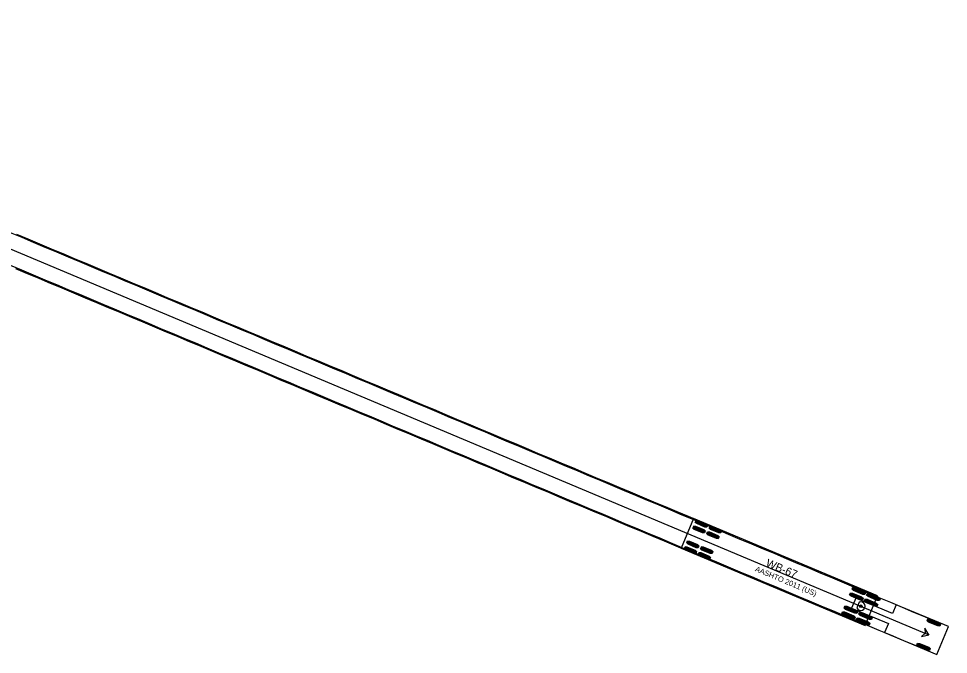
# Model space of a CAD drawing. Extents: x 916040 to 917457, y 328936 to 330267.
# Drawn here: x 917210 to 917456.8, y 329403.5 to 329572.2 of the extents above; entities that cross this region are included whole.
import ezdxf

# ---------------------------------------------------------------- set-up
doc = ezdxf.new("R2010")
doc.units = 0
doc.layers.add('NB_RightontoRoute25_WB67', color=7, linetype='Continuous')
doc.layers.add('NB_ThruontoManchester_WB67', color=7, linetype='Continuous')

msp = doc.modelspace()

# ---------------------------------------------------------------- linework, layer by layer
at = {"layer": 'NB_RightontoRoute25_WB67'}
for p, q in [((917062.28, 329572.24), (917451.54, 329408.71)), ((917389.11, 329439.55), (917385.82, 329431.71)), ((917437.97, 329419.02), (917389.11, 329439.55)), ((917392.67, 329437.31), (917389.63, 329438.59)), ((917392.76, 329437.52), (917389.71, 329438.8)), ((917392.85, 329437.73), (917389.8, 329439.01)), ((917392.03, 329435.79), (917388.99, 329437.06)), ((917392.12, 329436), (917389.08, 329437.28)), ((917392.21, 329436.21), (917389.16, 329437.49)), ((917395.72, 329434.24), (917392.67, 329435.52)), ((917395.81, 329434.45), (917392.76, 329435.73)), ((917395.89, 329434.66), (917392.85, 329435.94)), ((917396.36, 329435.76), (917393.31, 329437.04)), ((917396.44, 329435.97), (917393.4, 329437.25)), ((917396.53, 329436.18), (917393.49, 329437.46)), ((917390.37, 329431.84), (917387.33, 329433.12)), ((917390.46, 329432.05), (917387.42, 329433.33)), ((917390.55, 329432.26), (917387.5, 329433.54)), ((917385.82, 329431.71), (917434.68, 329411.18)), ((917389.73, 329430.32), (917386.69, 329431.59)), ((917389.82, 329430.53), (917386.78, 329431.81)), ((917389.91, 329430.74), (917386.87, 329432.02)), ((917393.6, 329429.19), (917390.55, 329430.47)), ((917394.06, 329430.29), (917391.02, 329431.57)), ((917394.15, 329430.5), (917391.1, 329431.78)), ((917394.24, 329430.71), (917391.19, 329431.99)), ((917393.42, 329428.77), (917390.38, 329430.05)), ((917393.51, 329428.98), (917390.46, 329430.26)), ((917434.6, 329419.42), (917431.22, 329420.84)), ((917434.69, 329419.63), (917431.3, 329421.05)), ((917434.77, 329419.84), (917431.39, 329421.26)), ((917433.96, 329417.9), (917430.58, 329419.32)), ((917434.05, 329418.11), (917430.67, 329419.53)), ((917434.13, 329418.32), (917430.75, 329419.74)), ((917432.18, 329418.4), (917431.07, 329415.76)), ((917441.95, 329414.29), (917432.18, 329418.4)), ((917438.01, 329416.7), (917434.63, 329418.12)), ((917434.68, 329411.18), (917437.97, 329419.02)), ((917438.47, 329417.8), (917435.09, 329419.22)), ((917438.56, 329418.01), (917435.18, 329419.43)), ((917438.65, 329418.22), (917435.27, 329419.64)), ((917437.97, 329419.02), (917437.97, 329419.02)), ((917432.49, 329414.41), (917429.11, 329415.83)), ((917432.58, 329414.62), (917429.2, 329416.04)), ((917432.67, 329414.84), (917429.29, 329416.26)), ((917431.07, 329415.76), (917440.84, 329411.65)), ((917433.13, 329417.32), (917432.5, 329415.83)), ((917437.83, 329416.27), (917434.45, 329417.69)), ((917437.92, 329416.49), (917434.54, 329417.91)), ((917442.95, 329416.66), (917441.95, 329414.29)), ((917456.77, 329410.85), (917442.95, 329416.66)), ((917431.85, 329412.89), (917428.47, 329414.31)), ((917431.94, 329413.1), (917428.56, 329414.52)), ((917432.03, 329413.31), (917428.65, 329414.73)), ((917435.9, 329411.69), (917432.52, 329413.11)), ((917436.36, 329412.79), (917432.98, 329414.21)), ((917436.45, 329413), (917433.07, 329414.42)), ((917436.54, 329413.21), (917433.16, 329414.63)), ((917435.73, 329411.26), (917432.34, 329412.69)), ((917435.81, 329411.48), (917432.43, 329412.9)), ((917440.84, 329411.65), (917439.85, 329409.28)), ((917454.51, 329411.06), (917451.13, 329412.48)), ((917454.6, 329411.27), (917451.22, 329412.69)), ((917454.69, 329411.48), (917451.31, 329412.9)), ((917453.68, 329403.48), (917456.77, 329410.85)), ((917456.77, 329410.85), (917456.77, 329410.85)), ((917439.85, 329409.28), (917453.68, 329403.48)), ((917451.77, 329404.53), (917448.39, 329405.95)), ((917451.86, 329404.74), (917448.48, 329406.16)), ((917451.94, 329404.95), (917448.56, 329406.37))]:
    msp.add_line(p, q, dxfattribs=at)
for points in [[(917207.73, 329515.48), (917210.8, 329514.19), (917213.87, 329512.89), (917216.95, 329511.6), (917220.02, 329510.31), (917223.1, 329509.02), (917226.17, 329507.73), (917229.25, 329506.44), (917232.32, 329505.14), (917235.4, 329503.85), (917238.47, 329502.56), (917241.55, 329501.27), (917244.62, 329499.98), (917247.7, 329498.69), (917250.77, 329497.39), (917253.85, 329496.1), (917256.92, 329494.81), (917260, 329493.52), (917263.07, 329492.23), (917266.14, 329490.94), (917269.22, 329489.64), (917272.29, 329488.35), (917275.37, 329487.06), (917278.44, 329485.77), (917281.52, 329484.48), (917284.59, 329483.19), (917287.67, 329481.89), (917290.74, 329480.6), (917293.82, 329479.31), (917296.89, 329478.02), (917299.97, 329476.73), (917303.04, 329475.44), (917306.12, 329474.14), (917309.19, 329472.85), (917312.27, 329471.56), (917315.34, 329470.27), (917318.41, 329468.98), (917321.49, 329467.69), (917324.56, 329466.39), (917327.64, 329465.1), (917330.71, 329463.81), (917333.79, 329462.52), (917336.86, 329461.23), (917339.94, 329459.93), (917343.01, 329458.64), (917346.09, 329457.35), (917349.16, 329456.06), (917352.24, 329454.77), (917355.31, 329453.48), (917358.39, 329452.18), (917361.46, 329450.89), (917364.54, 329449.6), (917367.61, 329448.31), (917370.68, 329447.02), (917373.76, 329445.73), (917376.83, 329444.43), (917379.91, 329443.14), (917382.98, 329441.85), (917386.06, 329440.56), (917389.13, 329439.27), (917392.21, 329437.98), (917395.28, 329436.68), (917398.36, 329435.39), (917401.43, 329434.1), (917404.51, 329432.81), (917407.58, 329431.52), (917410.66, 329430.23), (917413.73, 329428.93), (917416.81, 329427.64), (917419.88, 329426.35), (917422.95, 329425.06), (917426.03, 329423.77), (917429.1, 329422.48), (917432.18, 329421.18), (917435.25, 329419.89), (917438.33, 329418.6), (917441.4, 329417.31), (917444.48, 329416.02), (917447.55, 329414.73), (917450.63, 329413.43), (917453.09, 329412.4)], [(917209.38, 329515.03), (917212.46, 329513.74), (917215.53, 329512.45), (917218.61, 329511.16), (917221.68, 329509.87), (917224.76, 329508.58), (917227.83, 329507.29), (917230.91, 329506), (917233.98, 329504.71), (917237.06, 329503.42), (917240.13, 329502.12), (917243.21, 329500.83), (917246.28, 329499.54), (917249.36, 329498.25), (917252.43, 329496.96), (917255.51, 329495.67), (917258.58, 329494.38), (917261.66, 329493.09), (917264.73, 329491.79), (917267.81, 329490.5), (917270.88, 329489.21), (917273.96, 329487.92), (917277.03, 329486.63), (917280.11, 329485.34), (917283.18, 329484.05), (917286.26, 329482.75), (917289.33, 329481.46), (917292.41, 329480.17), (917295.48, 329478.88), (917298.55, 329477.59), (917301.63, 329476.3), (917304.7, 329475.01), (917307.78, 329473.71), (917310.85, 329472.42), (917313.93, 329471.13), (917317, 329469.84), (917320.08, 329468.55), (917323.15, 329467.26), (917326.23, 329465.96), (917329.3, 329464.67), (917332.38, 329463.38), (917335.45, 329462.09), (917338.53, 329460.8), (917341.6, 329459.51), (917344.68, 329458.21), (917347.75, 329456.92), (917350.83, 329455.63), (917353.9, 329454.34), (917356.98, 329453.05), (917360.05, 329451.76), (917363.12, 329450.46), (917366.2, 329449.17), (917369.27, 329447.88), (917372.35, 329446.59), (917375.42, 329445.3), (917378.5, 329444.01), (917381.57, 329442.71), (917384.65, 329441.42), (917387.72, 329440.13), (917390.8, 329438.84), (917393.26, 329437.81)], [(917207.7, 329506.81), (917210.78, 329505.52), (917213.85, 329504.23), (917216.93, 329502.94), (917220, 329501.64), (917223.07, 329500.35), (917226.15, 329499.06), (917229.22, 329497.77), (917232.3, 329496.48), (917235.37, 329495.19), (917238.45, 329493.89), (917241.52, 329492.6), (917244.6, 329491.31), (917247.67, 329490.02), (917250.75, 329488.73), (917253.82, 329487.44), (917256.9, 329486.14), (917259.97, 329484.85), (917263.05, 329483.56), (917266.12, 329482.27), (917269.2, 329480.98), (917272.27, 329479.69), (917275.34, 329478.39), (917278.42, 329477.1), (917281.49, 329475.81), (917284.57, 329474.52), (917287.64, 329473.23), (917290.72, 329471.93), (917293.79, 329470.64), (917296.87, 329469.35), (917299.94, 329468.06), (917303.02, 329466.77), (917306.09, 329465.48), (917309.17, 329464.18), (917312.24, 329462.89), (917315.32, 329461.6), (917318.39, 329460.31), (917321.47, 329459.02), (917324.54, 329457.73), (917327.61, 329456.43), (917330.69, 329455.14), (917333.76, 329453.85), (917336.84, 329452.56), (917339.91, 329451.27), (917342.99, 329449.98), (917346.06, 329448.68), (917349.14, 329447.39), (917352.21, 329446.1), (917355.29, 329444.81), (917358.36, 329443.52), (917361.44, 329442.23), (917364.51, 329440.93), (917367.59, 329439.64), (917370.66, 329438.35), (917373.74, 329437.06), (917376.81, 329435.77), (917379.88, 329434.48), (917382.96, 329433.18), (917386.03, 329431.89), (917389.11, 329430.6), (917392.18, 329429.31), (917395.26, 329428.02), (917398.33, 329426.73), (917401.41, 329425.43), (917404.48, 329424.14), (917407.56, 329422.85), (917410.63, 329421.56), (917413.71, 329420.27), (917416.78, 329418.97), (917419.86, 329417.68), (917422.93, 329416.39), (917426.01, 329415.1), (917429.08, 329413.81), (917432.15, 329412.52), (917435.23, 329411.22), (917438.3, 329409.93), (917441.38, 329408.64), (917444.45, 329407.35), (917447.53, 329406.06), (917449.99, 329405.02)], [(917209.17, 329505.9), (917212.24, 329504.61), (917215.32, 329503.32), (917218.39, 329502.03), (917221.47, 329500.74), (917224.54, 329499.45), (917227.62, 329498.16), (917230.69, 329496.87), (917233.77, 329495.58), (917236.84, 329494.29), (917239.92, 329493), (917242.99, 329491.71), (917246.07, 329490.41), (917249.14, 329489.12), (917252.22, 329487.83), (917255.29, 329486.54), (917258.37, 329485.25), (917261.44, 329483.96), (917264.52, 329482.67), (917267.59, 329481.38), (917270.66, 329480.08), (917273.74, 329478.79), (917276.81, 329477.5), (917279.89, 329476.21), (917282.96, 329474.92), (917286.04, 329473.63), (917289.11, 329472.33), (917292.19, 329471.04), (917295.26, 329469.75), (917298.34, 329468.46), (917301.41, 329467.17), (917304.49, 329465.88), (917307.56, 329464.59), (917310.64, 329463.29), (917313.71, 329462), (917316.79, 329460.71), (917319.86, 329459.42), (917322.94, 329458.13), (917326.01, 329456.84), (917329.09, 329455.54), (917332.16, 329454.25), (917335.23, 329452.96), (917338.31, 329451.67), (917341.38, 329450.38), (917344.46, 329449.09), (917347.53, 329447.79), (917350.61, 329446.5), (917353.68, 329445.21), (917356.76, 329443.92), (917359.83, 329442.63), (917362.91, 329441.34), (917365.98, 329440.04), (917369.06, 329438.75), (917372.13, 329437.46), (917375.21, 329436.17), (917378.28, 329434.88), (917381.36, 329433.59), (917384.43, 329432.29), (917387.5, 329431), (917389.96, 329429.97)]]:
    msp.add_lwpolyline(points, dxfattribs=at)
for points in [[(917392.87, 329437.78), (917392.65, 329437.26), (917392.15, 329437.28), (917389.96, 329438.2), (917389.6, 329438.53), (917389.82, 329439.06), (917390.32, 329439.04), (917392.51, 329438.12)], [(917392.23, 329436.26), (917392.01, 329435.73), (917391.51, 329435.75), (917389.32, 329436.67), (917388.96, 329437.01), (917389.19, 329437.54), (917389.68, 329437.52), (917391.87, 329436.6)], [(917395.92, 329434.71), (917395.69, 329434.18), (917395.2, 329434.2), (917393.01, 329435.13), (917392.65, 329435.46), (917392.87, 329435.99), (917393.37, 329435.97), (917395.56, 329435.05)], [(917396.56, 329436.23), (917396.33, 329435.71), (917395.84, 329435.73), (917393.65, 329436.65), (917393.29, 329436.98), (917393.51, 329437.51), (917394.01, 329437.49), (917396.2, 329436.57)], [(917390.57, 329432.31), (917390.35, 329431.78), (917389.86, 329431.8), (917387.66, 329432.73), (917387.31, 329433.06), (917387.53, 329433.59), (917388.02, 329433.57), (917390.21, 329432.65)], [(917389.93, 329430.79), (917389.71, 329430.26), (917389.22, 329430.28), (917387.03, 329431.2), (917386.67, 329431.54), (917386.89, 329432.07), (917387.38, 329432.05), (917389.57, 329431.13)], [(917393.62, 329429.24), (917393.4, 329428.71), (917392.9, 329428.73), (917390.71, 329429.65), (917390.35, 329429.99), (917390.58, 329430.52), (917391.07, 329430.5), (917393.26, 329429.58)], [(917394.26, 329430.76), (917394.04, 329430.24), (917393.54, 329430.26), (917391.35, 329431.18), (917390.99, 329431.51), (917391.21, 329432.04), (917391.71, 329432.02), (917393.9, 329431.1)], [(917434.8, 329419.9), (917434.57, 329419.37), (917434.03, 329419.41), (917431.6, 329420.43), (917431.19, 329420.79), (917431.42, 329421.32), (917431.96, 329421.28), (917434.39, 329420.25)], [(917434.16, 329418.38), (917433.94, 329417.85), (917433.4, 329417.89), (917430.96, 329418.91), (917430.55, 329419.27), (917430.78, 329419.8), (917431.32, 329419.76), (917433.75, 329418.73)], [(917438.03, 329416.75), (917437.81, 329416.22), (917437.27, 329416.26), (917434.83, 329417.28), (917434.43, 329417.64), (917434.65, 329418.17), (917435.19, 329418.13), (917437.62, 329417.11)], [(917438.67, 329418.27), (917438.45, 329417.74), (917437.91, 329417.78), (917435.47, 329418.81), (917435.07, 329419.16), (917435.29, 329419.69), (917435.83, 329419.65), (917438.26, 329418.63)], [(917432.69, 329414.89), (917432.47, 329414.36), (917431.93, 329414.4), (917429.5, 329415.42), (917429.09, 329415.78), (917429.31, 329416.31), (917429.85, 329416.27), (917432.29, 329415.25)], [(917432.05, 329413.37), (917431.83, 329412.84), (917431.29, 329412.88), (917428.86, 329413.9), (917428.45, 329414.26), (917428.67, 329414.79), (917429.21, 329414.75), (917431.65, 329413.72)], [(917435.92, 329411.74), (917435.7, 329411.21), (917435.16, 329411.25), (917432.73, 329412.27), (917432.32, 329412.63), (917432.54, 329413.16), (917433.08, 329413.12), (917435.52, 329412.1)], [(917436.56, 329413.26), (917436.34, 329412.73), (917435.8, 329412.77), (917433.37, 329413.8), (917432.96, 329414.15), (917433.18, 329414.68), (917433.72, 329414.64), (917436.16, 329413.62)], [(917454.71, 329411.53), (917454.49, 329411), (917453.95, 329411.04), (917451.51, 329412.07), (917451.11, 329412.42), (917451.33, 329412.95), (917451.87, 329412.91), (917454.3, 329411.89)], [(917451.54, 329408.71), (917450.55, 329410.45), (917450.62, 329409.1), (917449.6, 329408.2)], [(917451.97, 329405), (917451.75, 329404.47), (917451.21, 329404.51), (917448.77, 329405.54), (917448.36, 329405.89), (917448.59, 329406.42), (917449.13, 329406.38), (917451.56, 329405.36)]]:
    msp.add_lwpolyline(points, close=True, dxfattribs=at)
for centre, radius in [((917393.26, 329437.81), 0.0417), ((917389.96, 329429.97), 0.0417), ((917433.56, 329416.26), 0.34), ((917453.09, 329412.4), 0.0417), ((917451.54, 329408.71), 0.0417), ((917449.99, 329405.02), 0.0417)]:
    msp.add_circle(centre, radius, dxfattribs=at)
msp.add_arc((917433.56, 329416.26), 1.14, 202.2123, 112.2123, dxfattribs=at)
at = {"layer": 'NB_ThruontoManchester_WB67'}
msp.add_line((917062.28, 329572.24), (917451.54, 329408.71), dxfattribs=at)

# ---------------------------------------------------------------- texts
at = {"layer": 'NB_RightontoRoute25_WB67'}
for s, height, p in [('WB-67', 2.125, (917408.12, 329426.95)), ('AASHTO 2011 (US)', 1.4167, (917405.33, 329425.63))]:
    msp.add_text(s, height=height, rotation=337.2127, dxfattribs=at).set_placement(p)

doc.saveas('drawing.dxf')
